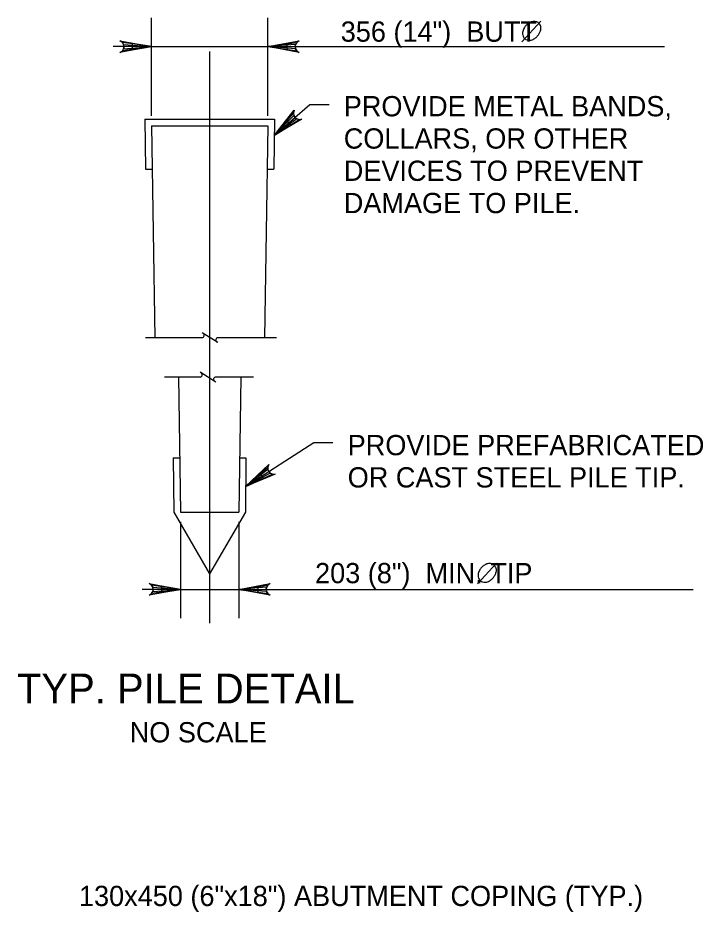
# Model space of a CAD drawing. Extents: x 635440 to 640306, y 296653 to 298484.
# Drawn here: x 638489.3 to 638590.8, y 297479.7 to 297612.1 of the extents above; entities that cross this region are included whole.
import ezdxf

# ---------------------------------------------------------------- set-up
doc = ezdxf.new("R2010")
doc.units = 0
doc.layers.add('4', color=7, linetype='Continuous')
doc.layers.add('5', color=7, linetype='Continuous')

msp = doc.modelspace()

# ---------------------------------------------------------------- linework, layer by layer
at = {"layer": '4'}
for p, q in [((638517.73, 297607.1), (638517.73, 297522.43)), ((638508.12, 297597.08), (638508.23, 297589.69)), ((638508.12, 297597.08), (638527.35, 297597.08)), ((638527.35, 297597.08), (638527.24, 297589.69)), ((638509.12, 297596.1), (638509.61, 297564.72)), ((638509.12, 297596.1), (638526.35, 297596.1)), ((638526.35, 297596.1), (638525.86, 297564.72)), ((638508.23, 297589.69), (638509.22, 297589.69)), ((638526.25, 297589.69), (638527.24, 297589.69)), ((638518.94, 297564), (638516.63, 297565.45)), ((638516.64, 297564.72), (638508.26, 297564.72)), ((638527.62, 297564.72), (638518.97, 297564.72)), ((638516.33, 297558.88), (638511.04, 297558.88)), ((638513.11, 297558.88), (638513.43, 297538.91)), ((638518.63, 297558.16), (638516.32, 297559.61)), ((638524.22, 297558.88), (638518.66, 297558.88)), ((638522.36, 297558.88), (638522.04, 297538.91)), ((638512.34, 297546.95), (638512.44, 297538.9)), ((638512.34, 297546.95), (638513.33, 297546.95)), ((638522.14, 297546.95), (638523.12, 297546.95)), ((638523.12, 297546.95), (638523.03, 297538.9)), ((638512.44, 297538.9), (638517.73, 297529.73)), ((638513.43, 297538.91), (638522.04, 297538.91)), ((638523.03, 297538.9), (638517.73, 297529.73))]:
    msp.add_line(p, q, dxfattribs=at)
for centre, start, end in [((638516.6, 297565.07), 275.3286, 57.8672), ((638518.97, 297564.38), 90, 240), ((638516.29, 297559.22), 275.3286, 57.8672), ((638518.66, 297558.54), 90, 240)]:
    msp.add_arc(centre, 0.341, start, end, dxfattribs=at)
at = {"layer": '5'}
for p, q in [((638509.12, 297597.58), (638509.12, 297612.09)), ((638526.35, 297597.58), (638526.35, 297612.09)), ((638563.99, 297608.53), (638566.79, 297611.6)), ((638509.12, 297607.84), (638503.45, 297607.84)), ((638509.12, 297607.84), (638585.09, 297607.84)), ((638526.35, 297607.84), (638532.02, 297607.84)), ((638527.32, 297594.7), (638532.58, 297599.26)), ((638532.58, 297599.26), (638535.42, 297599.26)), ((638523.07, 297542.7), (638533.15, 297549.2)), ((638533.15, 297549.2), (638535.99, 297549.2)), ((638513.43, 297537.44), (638513.43, 297523.2)), ((638522.04, 297537.44), (638522.04, 297523.2)), ((638557.4, 297528.26), (638560.2, 297531.32)), ((638513.43, 297527.45), (638507.76, 297527.45)), ((638513.43, 297527.45), (638589.35, 297527.45)), ((638524.88, 297527.45), (638527.71, 297527.45))]:
    msp.add_line(p, q, dxfattribs=at)
for points in [[(638509.12, 297607.84), (638504.46, 297606.97), (638504.82, 297607.21), (638505, 297607.53), (638505.06, 297607.84), (638505, 297608.15), (638504.82, 297608.46), (638504.46, 297608.71), (638509.12, 297607.84), (638504.82, 297608.46), (638505, 297608.15), (638509.12, 297607.84), (638505.06, 297607.84), (638505, 297607.53), (638509.12, 297607.84), (638504.82, 297607.21)], [(638526.35, 297607.84), (638531.01, 297608.71), (638530.65, 297608.46), (638530.47, 297608.15), (638530.41, 297607.84), (638530.47, 297607.53), (638530.65, 297607.21), (638531.01, 297606.97), (638526.35, 297607.84), (638530.65, 297607.21), (638530.47, 297607.53), (638526.35, 297607.84), (638530.41, 297607.84), (638530.47, 297608.15), (638526.35, 297607.84), (638530.65, 297608.46)], [(638527.32, 297594.7), (638530.27, 297598.41), (638530.16, 297597.99), (638530.22, 297597.63), (638530.39, 297597.36), (638530.63, 297597.16), (638530.98, 297597.04), (638531.41, 297597.09), (638527.32, 297594.7), (638530.98, 297597.04), (638530.63, 297597.16), (638527.32, 297594.7), (638530.39, 297597.36), (638530.22, 297597.63), (638527.32, 297594.7), (638530.16, 297597.99)], [(638523.07, 297542.7), (638526.52, 297545.96), (638526.35, 297545.56), (638526.36, 297545.2), (638526.49, 297544.9), (638526.7, 297544.67), (638527.03, 297544.51), (638527.46, 297544.49), (638523.07, 297542.7), (638527.03, 297544.51), (638526.7, 297544.67), (638523.07, 297542.7), (638526.49, 297544.9), (638526.36, 297545.2), (638523.07, 297542.7), (638526.35, 297545.56)], [(638513.43, 297527.45), (638508.77, 297526.58), (638509.12, 297526.83), (638509.31, 297527.14), (638509.36, 297527.45), (638509.31, 297527.76), (638509.12, 297528.08), (638508.77, 297528.32), (638513.43, 297527.45), (638509.12, 297528.08), (638509.31, 297527.76), (638513.43, 297527.45), (638509.36, 297527.45), (638509.31, 297527.14), (638513.43, 297527.45), (638509.12, 297526.83)], [(638522.04, 297527.45), (638526.7, 297528.32), (638526.35, 297528.08), (638526.16, 297527.76), (638526.11, 297527.45), (638526.16, 297527.14), (638526.35, 297526.83), (638526.7, 297526.58), (638522.04, 297527.45), (638526.35, 297526.83), (638526.16, 297527.14), (638522.04, 297527.45), (638526.11, 297527.45), (638526.16, 297527.76), (638522.04, 297527.45), (638526.35, 297528.08)]]:
    msp.add_lwpolyline(points, dxfattribs=at)
for points in [[(638506.28, 297608.31), (638506.28, 297607.37), (638509.12, 297607.84)], [(638529.19, 297608.31), (638529.19, 297607.37), (638526.35, 297607.84)], [(638529.77, 297596.2), (638529.15, 297596.91), (638527.32, 297594.7)], [(638525.73, 297543.85), (638525.22, 297544.65), (638523.09, 297542.71)], [(638510.59, 297527.92), (638510.59, 297526.98), (638513.43, 297527.45)], [(638524.88, 297527.92), (638524.88, 297526.98), (638522.04, 297527.45)]]:
    msp.add_lwpolyline(points, close=True, dxfattribs=at)
for points in [[(638566.5, 297611.29), (638566.28, 297611.47), (638566.07, 297611.52), (638565.79, 297611.55), (638565.63, 297611.55), (638565.37, 297611.49), (638565.12, 297611.37), (638564.95, 297611.28), (638564.62, 297611.01), (638564.36, 297610.67), (638564.2, 297610.36), (638564.11, 297610.07), (638564.08, 297609.8), (638564.11, 297609.57), (638564.22, 297609.24), (638564.34, 297609.07), (638564.58, 297608.89), (638564.94, 297608.8), (638565.36, 297608.81), (638565.88, 297609.05), (638566.26, 297609.38), (638566.55, 297609.77), (638566.73, 297610.19), (638566.8, 297610.65), (638566.72, 297610.95), (638566.52, 297611.29)], [(638559.91, 297531.02), (638559.69, 297531.19), (638559.48, 297531.25), (638559.2, 297531.28), (638559.04, 297531.28), (638558.78, 297531.21), (638558.53, 297531.1), (638558.36, 297531), (638558.03, 297530.74), (638557.77, 297530.4), (638557.61, 297530.09), (638557.52, 297529.8), (638557.49, 297529.53), (638557.52, 297529.3), (638557.63, 297528.97), (638557.75, 297528.8), (638557.99, 297528.61), (638558.35, 297528.53), (638558.77, 297528.54), (638559.29, 297528.78), (638559.67, 297529.1), (638559.96, 297529.5), (638560.14, 297529.92), (638560.21, 297530.38), (638560.13, 297530.67), (638559.93, 297531.02)]]:
    msp.add_spline(points, degree=3, dxfattribs=at)

# ---------------------------------------------------------------- texts
for s, height, p in [('356 (14")  BUTT', 3.0001, (638537.15, 297608.56)), ('PROVIDE METAL BANDS,', 3.0001, (638537.6, 297597.51)), ('COLLARS, OR OTHER ', 3.0001, (638537.6, 297592.73)), ('DEVICES TO PREVENT', 3.0001, (638537.6, 297587.95)), ('DAMAGE TO PILE.', 3.0001, (638537.6, 297583.17)), ('PROVIDE PREFABRICATED', 3.0001, (638538.18, 297547.32)), ('OR CAST STEEL PILE TIP.', 3.0001, (638538.18, 297542.54)), ('203 (8")  MIN. TIP', 3.0001, (638533.35, 297528.36)), ('TYP. PILE DETAIL', 4.4294, (638489.2, 297510.55)), ('NO SCALE', 3, (638505.9, 297504.79)), ('130x450 (6"x18") ABUTMENT COPING (TYP.)', 3.0001, (638498.38, 297480.55))]:
    msp.add_text(s, height=height, dxfattribs=at).set_placement(p)

doc.saveas('drawing.dxf')
